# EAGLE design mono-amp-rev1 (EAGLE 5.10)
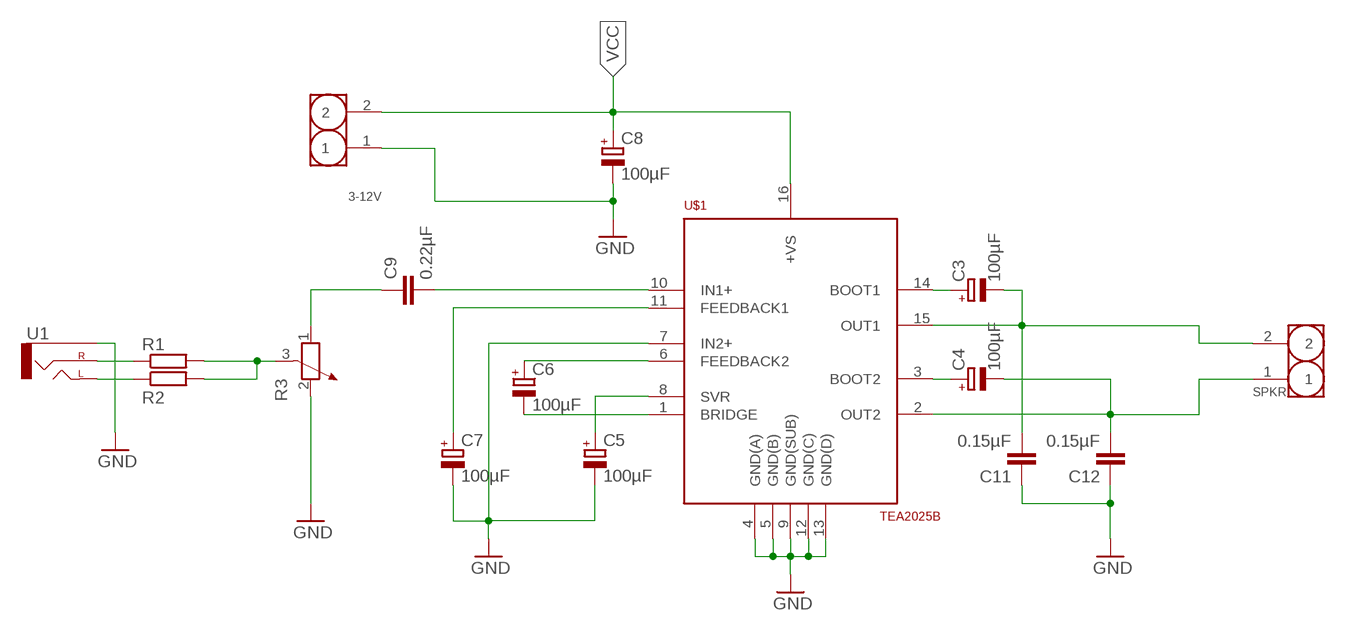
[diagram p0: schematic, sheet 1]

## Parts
3-12V  HEADER-2P-2.54  [2P-2.54]
C3  100µF  CPOL-EUE2.5-7  [E2,5-7]
C4  100µF  CPOL-EUE2.5-7  [E2,5-7]
C5  100µF  CPOL-EUE2.5-7  [E2,5-7]
C6  100µF  CPOL-EUE2.5-7  [E2,5-7]
C7  100µF  CPOL-EUE2.5-7  [E2,5-7]
C8  100µF  CPOL-EUE2.5-7  [E2,5-7]
C9  0.22µF  C-EU050-024X044  [C050-024X044]
C11  0.15µF  C-EU050-024X044  [C050-024X044]
C12  0.15µF  C-EU050-024X044  [C050-024X044]
R1  R-EU_0207/10  [0207/10]
R2  R-EU_0207/10  [0207/10]
R3  POTENTIOMETER_PT-10S  [PT-10S]
SPKR  HEADER-2P-2.54  [2P-2.54]
U1  AUDIO-JACKPTH  [AUDIO-JACK]
U$1  TEA2025B  [DIL16]

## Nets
GND [PWR]: 3-12V.1 C5.- C7.- C8.- C11.1 C12.1 R3.2 U1.SLEEVE U$1.4(GND(A)) U$1.5(GND(B)) U$1.7(IN2+) U$1.9(GND(SUB)) U$1.12(GND(C)) U$1.13(GND(D))
N$1: C9.2 U$1.10(IN1+)
N$2: C6.- U$1.1(BRIDGE)
N$3: C7.+ U$1.11(FEEDBACK1)
N$4: C6.+ U$1.6(FEEDBACK2)
N$5: C5.+ U$1.8(SVR)
N$6: C3.+ U$1.14(BOOT1)
N$7: C4.+ U$1.3(BOOT2)
N$10: C9.1 R3.1
N$12: R2.1 U1.TIP(LEFT)
N$13: R1.1 U1.RING(RIGHT)
N$16: R1.2 R2.2 R3.3
SPKR1 [SPKR]: C3.- C11.2 SPKR.2 U$1.15(OUT1)
SPKR2 [SPKR]: C4.- C12.2 SPKR.1 U$1.2(OUT2)
VCC [PWR]: 3-12V.2 C8.+ U$1.16(+VS)

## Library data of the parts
3-12V SPKR = Seeed-Connector:HEADER-2P
C3-C8 = rcl:CPOL-EU: POLARIZED CAPACITOR, European symbol
C9 C11 C12 = rcl:C-EU: CAPACITOR, European symbol
R1 R2 = resistor:R-EU_: RESISTOR, European symbol
R3 = rcl:POTENTIOMETER_: Potentiometer
U1 = SparkFun:AUDIO-JACK: 3.5mm Audio Jack Simple 3.5mm common PCB mount audio jack. SKU: PRT-08032
U$1 = build-electronic-circuits:TEA2025B

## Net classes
0 default: width 0.406 mm
1 SPKR: width 0.61 mm
2 PWR: width 0.61 mm

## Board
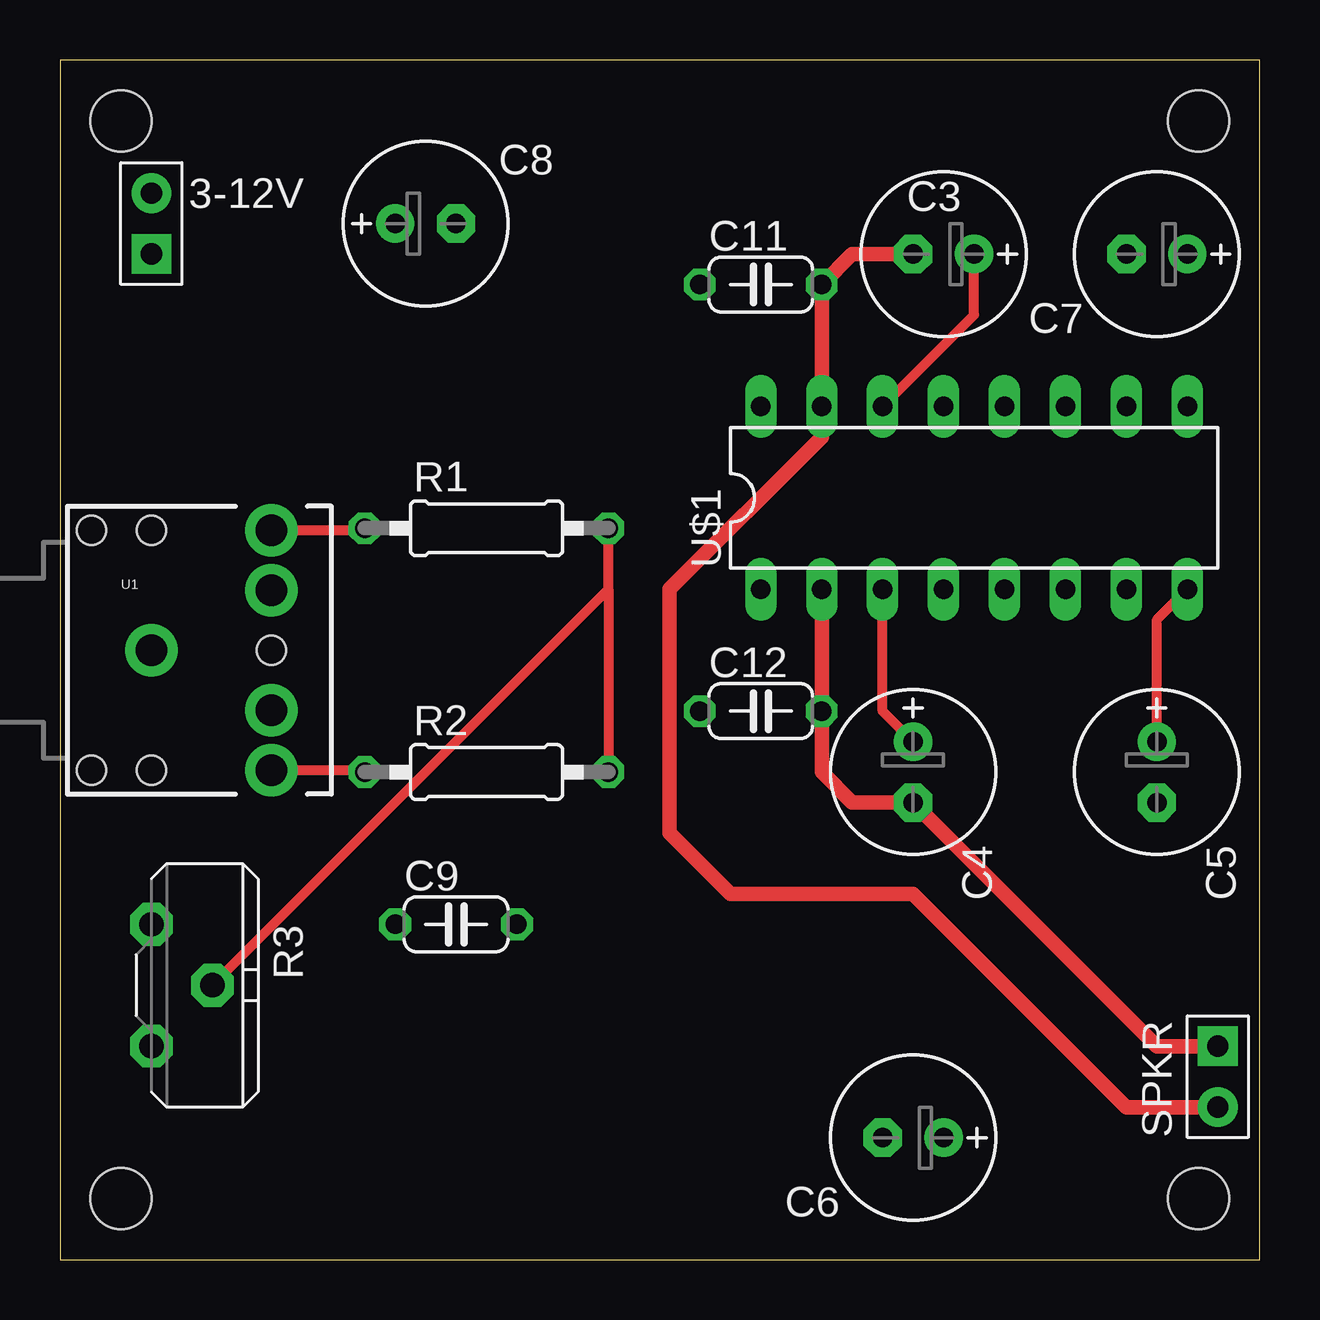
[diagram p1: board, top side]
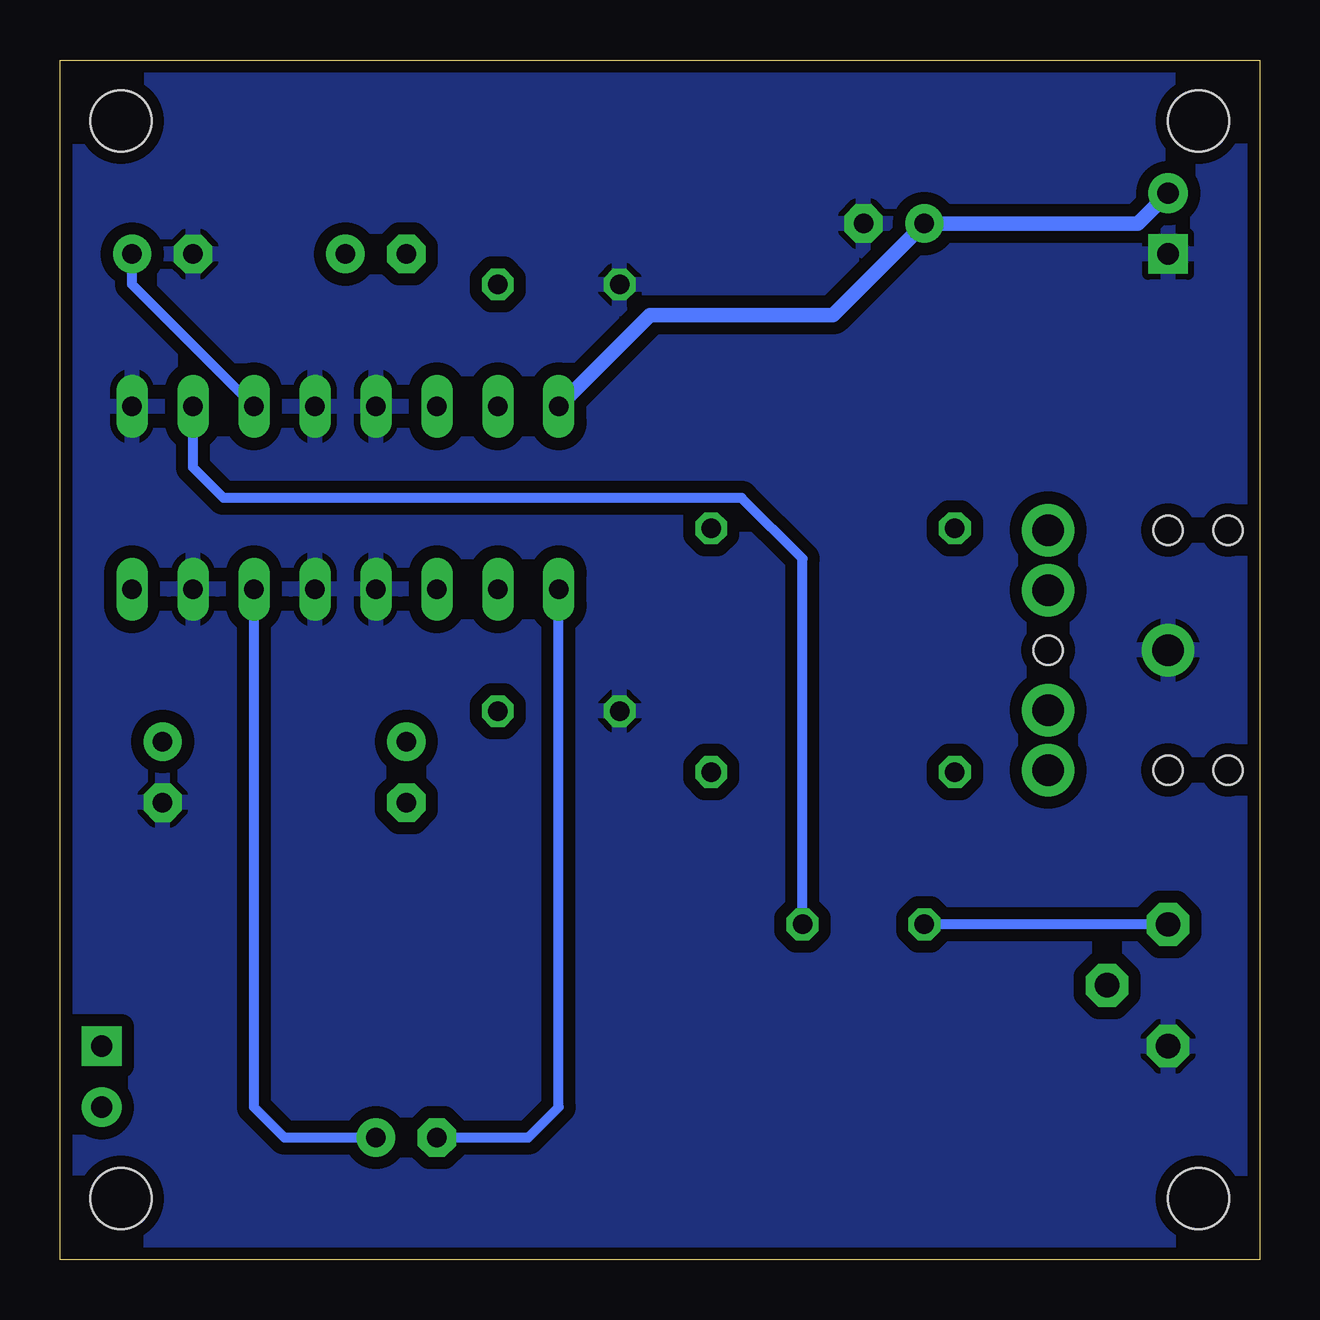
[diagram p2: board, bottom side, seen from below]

Size 50 x 50 mm. Coordinates in mm from the lower left corner, seen from the top.
Outline: 0,0 50,0 50,50 0,50 0,0
Copper layers (1*16): Top 0.035mm / dielectric 1.5mm / Bottom 0.035mm
Design rules "Fusion_eagle_rule_v1.1": minimum track width 6mil, minimum drill 12mil, track to track 6mil, track to pad 6mil, pad to pad 6mil, via to via 6mil, smd to smd 0mil, copper to edge 10mil, drill to drill 10mil, minimum pad ring 10mil, minimum via ring 6mil, stop-mask expansion 2mil, vias tented up to drill 100mil, thermal gap 10mil
Holes 2.54 mm at 2.54,2.54 2.54,47.46 47.46,47.46 47.46,2.54

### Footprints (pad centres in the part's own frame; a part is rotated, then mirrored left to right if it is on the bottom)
2P-2.54 = drill 0.889 pad 1.651 square: 1 0,1.27 | drill 0.889 pad 1.651 round: 2 0,-1.27
E2,5-7 = drill 0.813 pad 1.6 round: + -1.27,0 | drill 0.813 pad 1.6 octagon: - 1.27,0
C050-024X044 = drill 0.813 octagon: 1 -2.54,0; 2 2.54,0
0207/10 = drill 0.813 octagon: 1 -5.08,0; 2 5.08,0
PT-10S = drill 1.016 pad 1.778 octagon: 1 -2.54,-1.27; 2 2.54,-1.27; 3 0,1.27
AUDIO-JACK = drill 1.3 pad 2.184 round: RING 5,5; RSH 5,2.5; SLEEVE 0,0; TIP 5,-5; TSH 5,-2.5 | hole 1.2: 0,5; -2.5,5; -2.5,-5; 0,-5; 5,0
DIL16 = drill 0.813 long: 1 -8.89,-3.81; 2 -6.35,-3.81; 3 -3.81,-3.81; 4 -1.27,-3.81; 5 1.27,-3.81; 6 3.81,-3.81; 7 6.35,-3.81; 8 8.89,-3.81; 9 8.89,3.81; 10 6.35,3.81; 11 3.81,3.81; 12 1.27,3.81; 13 -1.27,3.81; 14 -3.81,3.81; 15 -6.35,3.81; 16 -8.89,3.81

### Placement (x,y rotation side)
3-12V  3.81,43.18 180 top
C3  36.83,41.91 180 top
C4  35.56,20.32 270 top
C5  45.72,20.32 270 top
C6  35.56,5.08 180 top
C7  45.72,41.91 180 top
C8  15.24,43.18 0 top
C9  16.51,13.97 0 top
C11  29.21,40.64 0 top
C12  29.21,22.86 0 top
R1  17.78,30.48 0 top
R2  17.78,20.32 0 top
R3  5.08,11.43 270 top
SPKR  48.26,7.62 0 top
U1  3.81,25.4 0 top
U$1  38.1,31.75 0 top

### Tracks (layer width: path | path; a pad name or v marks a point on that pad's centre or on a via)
GND
  pour Bottom (isolate 0.508): 0.25,0.25 0.25,49.75 49.75,49.75 49.75,0.25
N$1
  Bottom 0.406: C9.2 19.05,29.21 21.59,31.75 43.18,31.75 44.45,33.02 U$1.10
N$2
  Bottom 0.406: U$1.1 29.21,6.35 30.48,5.08 C6.-
N$3
  Bottom 0.406: U$1.11 46.99,40.64 C7.+
N$4
  Bottom 0.406: U$1.6 41.91,6.35 40.64,5.08 C6.+
N$5
  Top 0.406: U$1.8 45.72,26.67 C5.+
N$6
  Top 0.406: U$1.14 38.1,39.37 C3.+
N$7
  Top 0.406: C4.+ 34.29,22.86 U$1.3
N$10
  Bottom 0.406: R3.1 C9.1
N$12
  Top 0.406: U1.TIP 12.62,20.4 R2.1
N$13
  Top 0.406: U1.RING 12.62,30.4 R1.1
N$16
  Top 0.406: 22.86,27.94 R2.2 | 22.86,27.94 R1.2 | R3.3 22.86,27.94
SPKR1
  Top 0.61: SPKR.2 44.45,6.35 35.56,15.24 27.94,15.24 25.4,17.78 25.4,27.94 31.75,34.29 U$1.15 C11.2 33.02,41.91 C3.-
SPKR2
  Top 0.61: U$1.2 C12.2 31.75,20.32 33.02,19.05 C4.- 45.72,8.89 SPKR.1
VCC
  Bottom 0.61: U$1.16 25.4,39.37 17.78,39.37 C8.+ 5.08,43.18 3-12V.2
